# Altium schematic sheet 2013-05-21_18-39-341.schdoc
size 382 x 152 mm; SheetNumber: 1; SheetTotal: 1
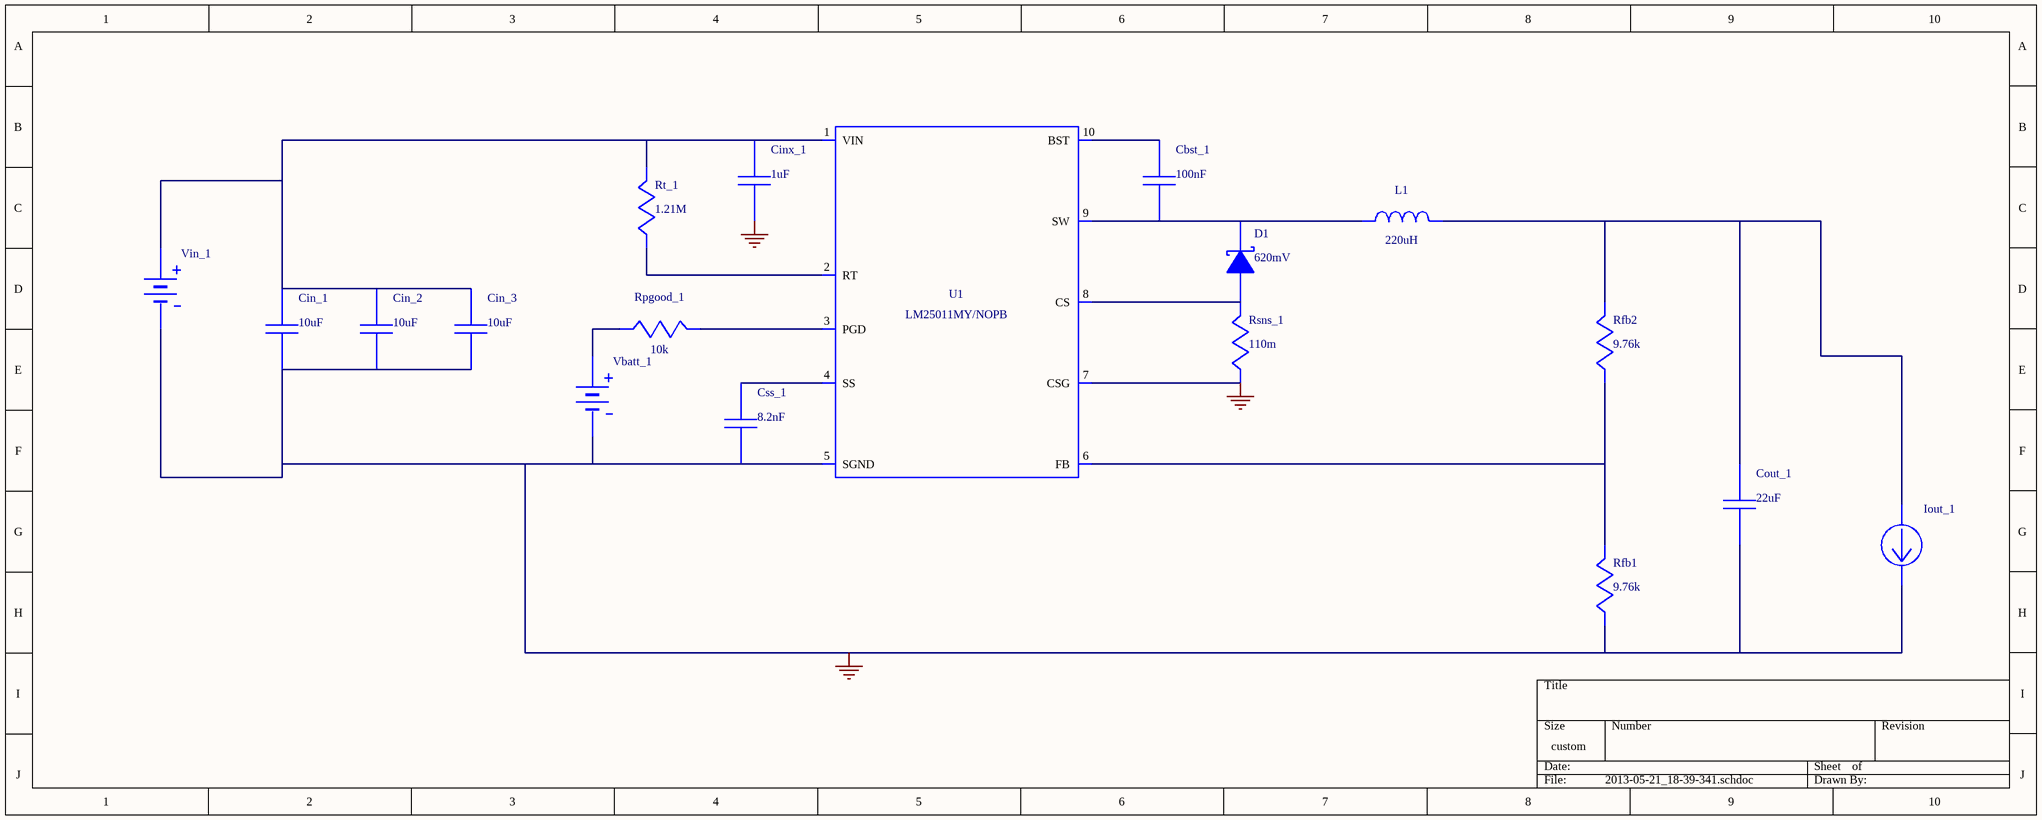
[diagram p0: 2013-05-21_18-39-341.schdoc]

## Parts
Cbst_1  value 100nF  (hidden comment: GRM21BR71E104KA01L)
Cin_1  value 10uF  (hidden comment: C5750X7S2A106M)
Cin_2  value 10uF  (hidden comment: C5750X7S2A106M)
Cin_3  value 10uF  (hidden comment: C5750X7S2A106M)
Cinx_1  value 1uF  (hidden comment: C3216X7R2A105M)
Cout_1  value 22uF  (hidden comment: C3216X5R0J226K)
Css_1  value 8.2nF  (hidden comment: GRM21BR72A822KA01L)
D1  value 620mV  (hidden comment: MBRS3100T3G)
Iout_1  WB_CURRENT_LOAD  (value not drawn)
L1  value 220uH  (hidden comment: PM2110-221K-RC)
Rfb1  value 9.76k  (hidden comment: CRCW04029K76FKED)
Rfb2  value 9.76k  (hidden comment: CRCW04029K76FKED)
Rpgood_1  value 10k  (hidden comment: CRCW080510K0FKEA)
Rsns_1  value 110m  (hidden comment: ERJ-2BSFR11X)
Rt_1  value 1.21M  (hidden comment: CRCW08051M21FKEA)
U1  LM25011MY/NOPB
Vbatt_1  WB_PRIMITIVE_BATTERY  (value not drawn)
Vin_1  WB_BATTERY  (value not drawn)

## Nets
0: Cin_1.2 Cin_2.2 Cin_3.2 Cinx_1.2 Cout_1.2 Css_1.2 Iout_1.2(-) Rfb1.2 Rsns_1.2 U1.5(SGND) U1.7(CSG) U1.11(DAP) Vbatt_1.2(-) Vin_1.2(-)
NetCbst_1_1: Cbst_1.1 U1.10(BST)
NetCbst_1_2: Cbst_1.2 D1.1(K) L1.2 U1.9(SW)
NetCin_1_1: Cin_1.1 Cin_2.1 Cin_3.1 Cinx_1.1 Rt_1.1 U1.1(VIN) Vin_1.1(+)
NetCout_1_1: Cout_1.1 Iout_1.1(+) L1.1 Rfb2.1
NetCss_1_1: Css_1.1 U1.4(SS)
NetD1_2: D1.2(A) Rsns_1.1 U1.8(CS)
NetRfb1_1: Rfb1.1 Rfb2.2 U1.6(FB)
NetRpgood_1_1: Rpgood_1.1 U1.3(PGD)
NetRpgood_1_2: Rpgood_1.2 Vbatt_1.1(+)
NetRt_1_2: Rt_1.2 U1.2(RT)

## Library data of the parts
Cbst_1 = GRM21BR71E104KA01L: GRM21BR71E104KA0; Manufacturer Name: MuRata
Cin_1-Cin_3 = C5750X7S2A106M: Manufacturer Name: TDK
Cinx_1 = C3216X7R2A105M: Manufacturer Name: TDK
Cout_1 = C3216X5R0J226K: Manufacturer Name: TDK
Css_1 = GRM21BR72A822KA01L: GRM21BR72A822KA0; Manufacturer Name: MuRata
D1 = MBRS3100T3G: Manufacturer Name: ON Semiconductor
Iout_1 = WB_CURRENT_LOAD: Value: UNLISTED
L1 = PM2110-221K-RC: Manufacturer Name: Bourns
Rfb1 Rfb2 = CRCW04029K76FKED: Manufacturer Name: Vishay-Dale
Rpgood_1 = CRCW080510K0FKEA: Manufacturer Name: Vishay-Dale
Rsns_1 = ERJ-2BSFR11X: Manufacturer Name: Panasonic
Rt_1 = CRCW08051M21FKEA: Manufacturer Name: Vishay-Dale
U1 = LM25011MY/NOPB: Manufacturer Name: Texas Instruments; Value: UNLISTED
Vbatt_1 = WB_PRIMITIVE_BATTERY: WB_PRIMITIVE_BAT; Value: UNLISTED
Vin_1 = WB_BATTERY: Value: UNLISTED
